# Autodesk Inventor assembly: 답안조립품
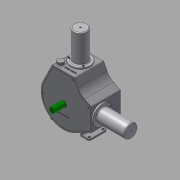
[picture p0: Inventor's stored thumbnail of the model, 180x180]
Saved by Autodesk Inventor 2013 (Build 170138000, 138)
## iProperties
Created: 2017-05
Part Number: 답안조립품
Document SubType Name: Assembly
Designer: dgall
Mass: 2156.82 g
Surface Area: 4005.96 cm^2
Volume: 952.79 cm^3
Density: 2.26369 g/cm^3
Author: dgall
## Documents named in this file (13)
- C:\Users\dgall\Desktop\370507V1022\답안조립품.iam
- C:\Users\dgall\Desktop\370507V1022\본체.ipt
- C:\Users\dgall\Desktop\370507V1022\앞커버.ipt
- C:\Users\dgall\Desktop\370507V1022\축.ipt
- C:\Users\dgall\Desktop\370507V1022\베어링 20 x 37 x 9.ipt
- C:\Users\dgall\Desktop\370507V1022\커넥팅로드.ipt
- C:\Users\dgall\Desktop\370507V1022\커넥팅로드 캡.ipt
- C:\Users\dgall\Desktop\370507V1022\측정게이지.ipt
- C:\Users\dgall\Desktop\370507V1022\실린더.ipt
- C:\Users\dgall\Desktop\370507V1022\피스톤.ipt
- C:\Users\dgall\Desktop\370507V1022\피스톤 핀.ipt
- C:\Users\dgall\Desktop\370507V1022\볼트 M3 x 12.ipt
- C:\Users\dgall\Desktop\370507V1022\너트 M3.ipt
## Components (4 placed, 2 different names)
1. 피스톤:1
2. 피스톤:2
3. 피스톤 핀:1
4. 피스톤 핀:2
